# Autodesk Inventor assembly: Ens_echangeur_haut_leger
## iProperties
Shininess: 64.0
Length Units: 11269
Angle Units: 11279
Time Units: 11290
Mass Units: 11283
Length Display Precision: 3
Angle Display Precision: 2
Compacted: True
Created: 2008-03
Part Number: Ens_echangeur_haut_leger
Document SubType Name: Assembly
Designer: Pascal
Density: 0.0
Volumn: 0.0
Area: 0.0
PropertySet Name: Model Information
Control State: 0
Master: False
Checked Out: False
DESIGNATION: Echangeur haut
Author: Pascal
